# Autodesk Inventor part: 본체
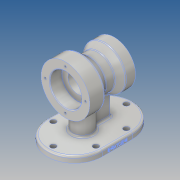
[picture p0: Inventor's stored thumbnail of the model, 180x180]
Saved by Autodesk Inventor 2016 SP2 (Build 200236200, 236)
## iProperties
Created: 2020-01
Part Number: 본체
Material: 알루미늄 6061
Document SubType Name: Modeling
Designer: EZ
Density: 2.7 g/cm^3
Appearance: 알루미늄 - 평지
Mass: 938.111 g
Surface Area: 654.887 cm^2
Volume: 347.449 cm^3
Author: EZ
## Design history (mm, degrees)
sketch "스케치1"
  geometry: L1 (0, 25)-(0, -25); L2 (-45, 25)-(-45, -25); L3 (45, -25)-(45, 25); A1 r 45 centre (0, 25) between (45, 25) and (-45, 25); A2 r 45 centre (0, -25) between (-45, -25) and (45, -25); 2 further points
  constraints: 8 end point, 4 point on circle, 4 tangent, 2 centre point, 2 coincident, 1 midpoint, 1 parallel, 1 vertical
  dimensions: "d0" = 50 distance of L1.end L1.start; "d1" = 45 radius of A1
extrude "돌출1" new body sketch "스케치1" distance "d2" = 10; taper "d3" = 0 deg
sketch "스케치2"
  geometry: L1 (120, 40)-(80, 40); L2 (80, 40)-(80, 16); L3 (80, 16)-(120, 16); L4 (120, 16)-(120, 40); L5 (115, -24)-(80, -24); L6 (80, -24)-(80, -40); L7 (80, -40)-(115, -40); L8 (115, -40)-(115, -24); L9 (10, -70)-(0, -70) reference; L10 (0, -70)-(0, 70) reference; L11 (0, 70)-(10, 70) reference; L12 (10, 70)-(10, -70) reference; L13 (107.5, 1.103)-(80, 1.103); L14 (80, 1.103)-(80, -13.289); L15 (80, -13.289)-(107.5, -13.289); L16 (107.5, -13.289)-(107.5, 1.103); L17 (107.5, -13.289)-(115, -24); L18 (107.5, 1.103)-(120, 16); L19 (80, 16)-(80, 1.103); L20 (80, -13.289)-(80, -24); 1 further point
  constraints: 32 end point, 6 parallel, 3 horizontal, 3 perpendicular, 1 collinear
  dimensions: "d4" = 80 distance from line of point (0, 0) L2; "d5" = 80 distance from line of point (0, 0) L6; "d6" = 80 diameter of L4 L2; "d7" = 24 distance between parallel lines of L3 L1; "d8" = 70 diameter of L8 L6; "d9" = 16 distance between parallel lines of L5 L7; "d10" = 30 distance between parallel lines of L11 L1; "d11" = 80 distance between parallel lines of L1 L7; "d12" = 55 diameter of L16 L14; "d13" = 40 deg angle of L16 L18; "d14" = 35 deg angle of L16 L17
revolve "회전1" sketch "스케치2" stored, may be unused: angle "d15" = 90 deg
sketch "스케치3"
  geometry: L1 (-45, -25)-(-45, 25) reference; L2 (45, 25)-(45, -25) reference; L3 (0, -70)-(66.928, -70); C1 r 16 at (0, -12); A1 r 45 centre (0, -25) between (-45, -25) and (45, -25) reference; A2 r 45 centre (0, 25) between (45, 25) and (-45, 25) reference; 2 further points
  constraints: 2 end point, 1 centre point, 1 coincident, 1 horizontal, 1 point on circle, 1 tangent
  dimensions: "d16" = 58 distance from line of point (0, -12) L3; "d17" = 32 diameter of C1
extrude "돌출2" join sketch "스케치3" stored distance "d18" = 0; taper "d19" = 0 deg
sketch "스케치4"
  geometry: L1 (10, -70)-(0, -70) reference; L2 (0, -70)-(0, 70) reference; L3 (0, 70)-(10, 70) reference; L4 (10, 70)-(10, 28) reference; L5 (10, 28)-(40, 28) reference; L6 (40, 28)-(40, 40) reference; L7 (40, 40)-(120, 40) reference; L8 (120, 40)-(120, 16) reference; L9 (120, 16)-(107.5, 1.103) reference; L10 (107.5, 1.103)-(107.5, -13.289) reference; L11 (107.5, -13.289)-(115, -24) reference; L12 (115, -24)-(115, -40) reference; L13 (115, -40)-(45, -40) reference; L14 (45, -40)-(45, -24) reference; L15 (45, -24)-(52.5, -13.289) reference; L16 (52.5, -13.289)-(52.5, -4) reference; L17 (52.5, -4)-(10, -4) reference; L18 (10, -4)-(10, -70) reference; L19 (45, -30)-(10, -30); 1 further point
  constraints: 2 end point, 2 point on line, 1 perpendicular
  dimensions: "d20" = 10 distance between parallel lines of L13 L19
feature "리브1" sketch "스케치4" dims "d21" = 1, "d22" = 10, "d23" = 0, "d24" = 0, "d25" = 1, "d26" = 1
fillet "모깎기1" dims "d27" = 3
fillet "모깎기2" dims "d28" = 3
sketch "스케치5"
  geometry: C1 r 20 at (0, 0); 1 further point
  constraints: 1 centre point
  dimensions: "d29" = 40 diameter of C1
extrude "돌출3" cut sketch "스케치5" distance "d30" = 17; taper "d31" = 0 deg
sketch "스케치6"
  geometry: C1 r 26 at (0, 0); 1 further point
  constraints: 1 centre point
  dimensions: "d32" = 52 diameter of C1
extrude "돌출4" cut sketch "스케치6" distance "d33" = 20; taper "d34" = 0 deg
sketch "스케치7"
  geometry: C1 r 16 at (0, 0); 1 further point
  constraints: 1 centre point
  dimensions: "d35" = 32 diameter of C1
extrude "돌출5" cut sketch "스케치7" stored distance "d36" = 20; taper "d37" = 0 deg
fillet "모깎기3" dims "d38" = 0.3
sketch "스케치8" dims "d39" = 55
  geometry: 3 further points
  constraints: 1 vertical alignment, 2 other
hole "구멍1" sketch "스케치8" at (0, 27.5) diameter "d40" = 3.242; stored, may be unused: countersink angle "d44" = 90 deg, drill point angle "d46" = 118 deg; dims "d41" = 9, "d42" = 4, "d43" = 2, "d45" = 11
sketch "스케치9" dims "d50" = 66
  geometry: 3 further points
  constraints: 1 vertical alignment, 2 other
hole "구멍2" sketch "스케치9" at (0, 33) diameter "d51" = 3.242; stored, may be unused: countersink angle "d55" = 90 deg, drill point angle "d57" = 118 deg; dims "d52" = 9, "d53" = 4, "d54" = 2, "d56" = 11
chamfer "모따기1" distance "d61" = 1; stored, may be unused: second distance "d62" = 2, angle "d63" = 45 deg
sketch "스케치10"
  geometry: L1 (8, 5.234)-(8, 27) reference; L2 (2, 33)-(-2, 33) reference; L3 (-8, 27)-(-8, 5.234) reference; L4 (-45, -25)-(-45, 25) reference; L5 (45, 25)-(45, -25) reference; L6 (0, -25)-(0, 25); L7 (35, -25)-(35, 25); L8 (-35, 25)-(-35, -25); A1 r 19 centre (0, -12) between (-8, 5.234) and (8, 5.234) reference; A2 r 6 centre (2, 27) between (8, 27) and (2, 33) reference; A3 r 6 centre (-2, 27) between (-2, 33) and (-8, 27) reference; A4 r 45 centre (0, -25) between (-45, -25) and (45, -25) reference; A5 r 45 centre (0, 25) between (45, 25) and (-45, 25) reference; A6 r 35 centre (0, -25) between (-35, -25) and (35, -25); A7 r 35 centre (0, 25) between (35, 25) and (-35, 25); 8 further points
  constraints: 8 end point, 6 point on circle, 4 coincident, 4 tangent, 2 centre point, 1 midpoint, 1 parallel, 1 vertical
  dimensions: "d67" = 35 radius of A7
hole "구멍3" sketch "스케치10" at (0, -60), (35, -25), (35, 25), (0, 60), (-35, -25), (-35, 25) diameter "d68" = 9; stored, may be unused: countersink angle "d72" = 90 deg, drill point angle "d74" = 118 deg; dims "d69" = 9, "d70" = 4, "d71" = 2, "d73" = 11
sketch "스케치11"
  geometry: L1 (50, 0)-(0, 0) reference; L2 (0, 0)-(0, 10) reference; L3 (0, 10)-(50, 10) reference; L4 (50, 0)-(50, 10) reference; L5 (-45, 0)-(-45, 10) reference; 2 further points
  constraints: 1 other
  dimensions: "d75" = 4 distance of point (25, 0) point (25, 4); "d76" = 70 distance from line of L5 point (25, 4)
feature "엠보싱1" sketch "스케치11" dims "d4" = 80, "d5" = 80, "d6" = 80, "d7" = 24, "d8" = 70, "d9" = 16, "d10" = 30, "d11" = 80, "d12" = 55, "d13" = 40 deg, "d14" = 35 deg, "d77" = 0.5, "d78" = 0
fillet "모깎기4" dims "d79" = 3
fillet "모깎기5" dims "d80" = 3
node "솔리드1"
pattern_circular "원형 패턴1" dims angle "d48" = 360 deg
pattern_circular "원형 패턴2" dims angle "d59" = 360 deg
node "절단 모서리 투영1"
node "절단 모서리 투영2"
node "절단 모서리 투영3"
node "절단 모서리 투영4"
node "절단 모서리 투영5"
